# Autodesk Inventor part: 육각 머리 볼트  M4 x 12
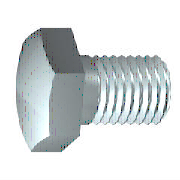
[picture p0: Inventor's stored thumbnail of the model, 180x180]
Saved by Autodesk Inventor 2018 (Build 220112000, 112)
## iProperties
IsCustomPart: 1
Created: 2012-02
Part Number: 육각 머리 볼트  M4 x 12
Material: 강철, 연강
Description: 6각 머리 나사
Document SubType Name: Modeling
Standard: ISO 4017
Designer: mdu-01
Standard Revision: Third edition 1999-08-15
Standards Organization: ISO
Language: ko-KR
Size Designation: M4 x 12
Categories: <MemberInstance><Categories><Category DisplayName="조임쇠" InternalName="e4da775c-781d-43d5-af7c-5136215cf5a6" Mnemonic="FSTN"><Category DisplayName="볼트" InternalN
Density: 7.75 g/cm^3
Appearance: 강철
Author: mdu-01
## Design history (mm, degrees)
sketch "스케치1"
  geometry: L1 (0, 3.015)-(0, 2); L2 (2.1, 2)-(12, 2); L3 (12, 2)-(12, 0); L4 (12, 0)-(-0.4, 0); L5 (-2.88, 0)-(14.48, 0) reference; L6 (-0.4, 0)-(-0.4, 3.015); L7 (-0.4, 3.015)-(0, 3.015); L8 (2.1, 2)-(1.67, 2); L9 (1.67, 2)-(0, 2); L10 (0, -0.603)-(0, 3.618) reference
  constraints: 16 end point, 2 collinear, 2 perpendicular, 1 parallel
  dimensions: "d0" = 12 distance between parallel lines of L3 L1 (= NLG); "d1" = 9.9 distance from line of L2.start L3 (= GEL); "d2" = 4 diameter of L2 L4 (= GD); "d9" = 0.4001 distance between parallel lines of L6 L1 (computed from SD); "d10" = 6.03 diameter of L7 L4 (= SD2); "d13" = 0.42952 distance of L2.start L8.end (computed from GAL); "d14" = 4 diameter of L9 L4 (= BDM)
revolve "본체" sketch "스케치1" stored, may be unused: angle "d12" = 90 deg
sketch "스케치2"
  geometry: L1 (0, 4.041)-(3.5, 2.021); L2 (3.5, 2.021)-(3.5, -2.021); L3 (3.5, -2.021)-(0, -4.041); L4 (0, -4.041)-(-3.5, -2.021); L5 (-3.5, -2.021)-(-3.5, 2.021); L6 (-3.5, 2.021)-(0, 4.041); 2 further points
  constraints: 12 end point, 1 coincident, 1 vertical, 11 other
  dimensions: "d11" = 7 distance between parallel lines of L5 L2 (= SW)
extrude "머리" join sketch "스케치2" distance "d3" = 2.4 (= KOH - SD); taper "d4" = 0 deg
sketch "스케치4"
  geometry: L1 (-2.8, 3.5)-(-2.8, 4.041); L2 (-2.8, 4.041)-(-2.487, 4.041); L3 (-2.487, 4.041)-(-2.8, 3.5); L4 (-3.28, 0)-(0.08, 0) reference; L5 (-0.4, 4.041)-(-2.8, 4.041) reference; L6 (-2.8, 2.021)-(-2.8, 4.041) reference
  constraints: 6 end point, 2 collinear, 1 perpendicular, 1 vertical
  dimensions: "d5" = 30 deg angle of L3 L1 (= ANG1); "d19" = 7 diameter of L1.start L4 (= SW0)
revolve "모따기1" sketch "스케치4" stored, may be unused: angle "d21" = 90 deg
workplane "Work Plane1"
body "Solid1"
feature "스레드" dims "d15" = 9.9 (= GEL), "d16" = 0
chamfer "모따기2" distance "d6" = 0.42941 (= -0.5 x SPD + 0.5 x GD); stored, may be unused: second distance "d7" = 0.42952 (computed from GUL), angle "d55" = 45 deg
other parameters: "NLG" = 12 [user parameter; used in 1 equation term], "GD" = 4 (= NND) [user parameter; used in 2 equation terms], "BDM" = 4 (= NND) [user parameter; used in 1 equation term], "KOH" = 2.8 [user parameter; used in 1 equation term], "GEL" = 9.9 [user parameter; used in 2 equation terms], "SW" = 7 [user parameter; used in 2 equation terms], "SW0" = 7 (= SW) [user parameter; used in 1 equation term], "SPD" = 3.14117 (= NND - 1.2269 x PTC) [user parameter; used in 1 equation term], "SD2" = 6.03 [user parameter; used in 2 equation terms], "SD" = 0.4 [user parameter; used in 2 equation terms], "ANG1" = 30 deg [user parameter; used in 1 equation term], "GAL" = 0.42941 (= 0.61345 x PTC) [user parameter; used in 1 equation term], "GUL" = 0.42941 (= 0.61345 x PTC) [user parameter; used in 1 equation term], "d8" = 0, "RR" = 0.2 [user parameter], "d57" = 0, "d58" = 0, "TPU" = 14.28571 (computed from PTC) [user parameter], "GD1" = 3.14117 (= THREADDIA - 1.2269 x PTC) [user parameter], "THREADDIA" = 4 [user parameter; used in 1 equation term], "SDH" = 6.03 (= SD2) [user parameter], "SDHG" = 2.1 [user parameter], "TOA" = 30 deg [user parameter], "PTC" = 0.7 [user parameter; used in 5 equation terms], "NND" = 4 [user parameter; used in 3 equation terms], "E0" = 8.085 [user parameter]
